// Mitsubishi GX Works2 project: MM-42MT-8MTS-F700-FX2N-A例程   PLC: FX2N/FX2NC

PROGRAM MAIN
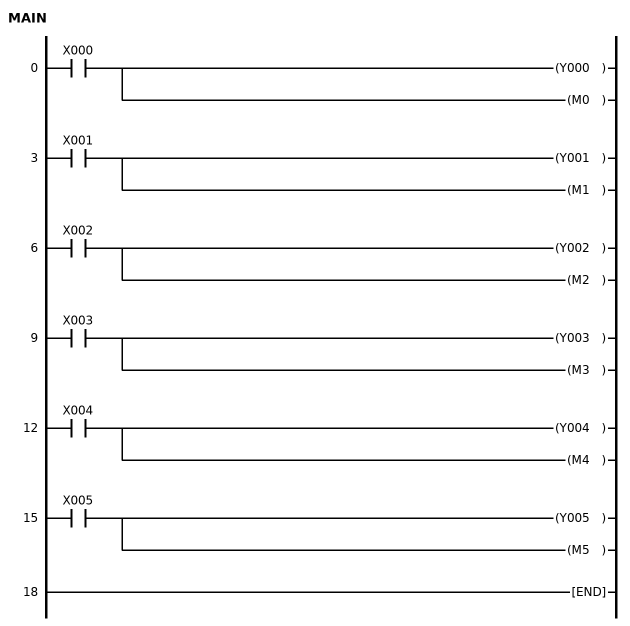
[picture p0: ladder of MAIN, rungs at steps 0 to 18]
0     LD      X000
      OUT     Y000
      OUT     M0
3     LD      X001
      OUT     Y001
      OUT     M1
6     LD      X002
      OUT     Y002
      OUT     M2
9     LD      X003
      OUT     Y003
      OUT     M3
12    LD      X004
      OUT     Y004
      OUT     M4
15    LD      X005
      OUT     Y005
      OUT     M5
18    END
END_PROGRAM
